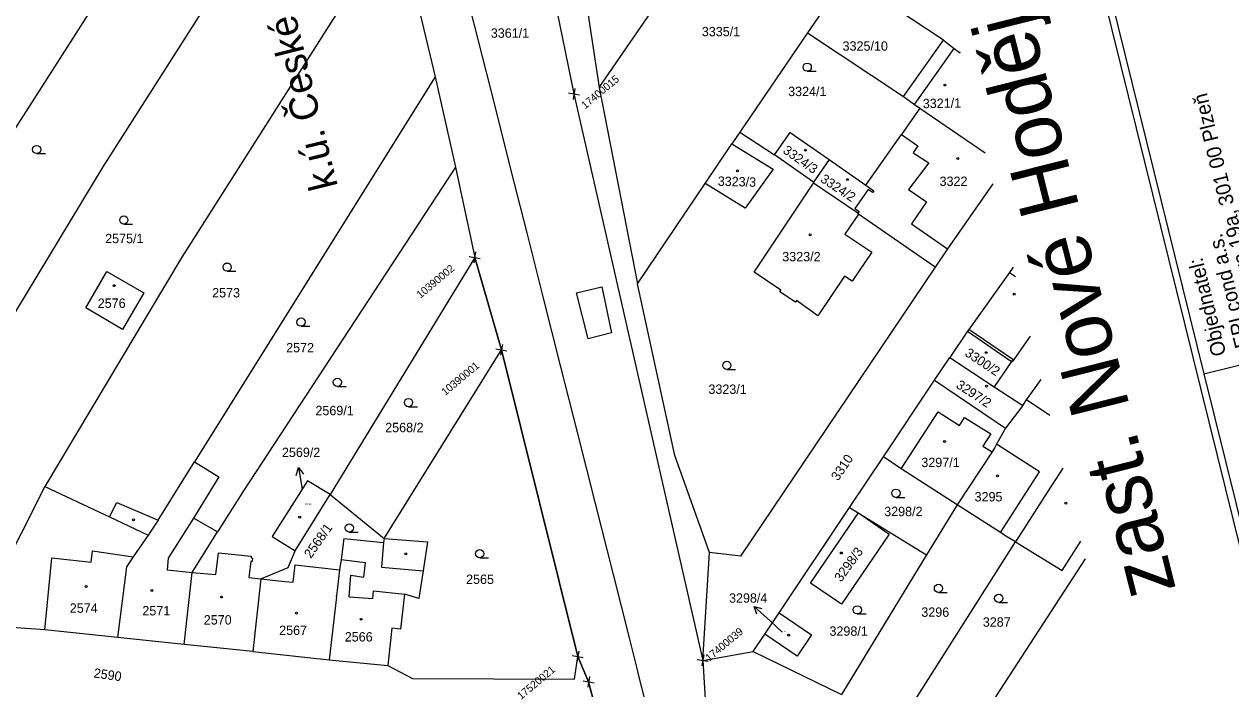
# Model space of a CAD drawing. Extents: x -754679 to -754173, y -1169241 to -1168288.
# Drawn here: x -754471.3 to -754307.2, y -1168949.2 to -1168858.8 of the extents above; entities that cross this region are included whole.
import ezdxf

# ---------------------------------------------------------------- set-up
doc = ezdxf.new("R2010")
doc.units = 0
for name, color, linetype in [('Vrstva 1', 7, 'Continuous'), ('Vrstva 16', 7, 'Continuous'), ('Vrstva 18', 7, 'Continuous'), ('Vrstva 19', 7, 'Continuous'), ('Vrstva 2', 7, 'Continuous'), ('Vrstva 23', 7, 'Continuous'), ('Vrstva 24', 7, 'Continuous'), ('Vrstva 25', 7, 'Continuous'), ('Vrstva 4', 7, 'Continuous'), ('Vrstva 52', 7, 'Continuous'), ('Vrstva 53', 7, 'Continuous'), ('Vrstva 60', 7, 'Continuous')]:
    doc.layers.add(name, color=color, linetype=linetype)

msp = doc.modelspace()

# ---------------------------------------------------------------- linework, layer by layer
at = {"layer": 'Vrstva 1'}
for p, q in [((-754477.37, -1168880.54), (-754443.28, -1168827.28)), ((-754393.12, -1168867.44), (-754373.15, -1168838.34)), ((-754420.6, -1168844.33), (-754449.89, -1168890.49)), ((-754420.6, -1168844.33), (-754415.45, -1168865.96)), ((-754401.41, -1168844.82), (-754396.56, -1168868.29)), ((-754396.3, -1168846.57), (-754393.12, -1168867.44)), ((-754460.56, -1168878.23), (-754444.22, -1168852.55)), ((-754359.46, -1168852.25), (-754364.83, -1168859.96)), ((-754346.33, -1168861), (-754359.46, -1168852.25)), ((-754364.83, -1168859.96), (-754374.01, -1168873.5)), ((-754364.83, -1168859.96), (-754351.77, -1168868.65)), ((-754346.33, -1168861), (-754344.87, -1168862.11)), ((-754350.27, -1168869.71), (-754344.87, -1168862.11)), ((-754344.87, -1168862.11), (-754344.14, -1168862.67)), ((-754344.07, -1168862.58), (-754344.14, -1168862.67)), ((-754344.14, -1168862.67), (-754344.03, -1168862.74)), ((-754415.45, -1168865.96), (-754448.17, -1168918.32)), ((-754415.45, -1168865.96), (-754412.65, -1168878.24)), ((-754396.56, -1168868.29), (-754379.05, -1168945.33)), ((-754393.12, -1168867.44), (-754387.93, -1168894.11)), ((-754351.77, -1168868.65), (-754350.27, -1168869.71)), ((-754350.27, -1168869.71), (-754349.52, -1168870.24)), ((-754349.52, -1168870.24), (-754352.02, -1168873.79)), ((-754349.52, -1168870.24), (-754340.67, -1168876.32)), ((-754374.01, -1168873.5), (-754375.09, -1168875.1)), ((-754374.01, -1168873.5), (-754369.28, -1168876.59)), ((-754369.28, -1168876.59), (-754367.16, -1168873.52)), ((-754367.16, -1168873.52), (-754361.87, -1168877.22)), ((-754356.89, -1168880.71), (-754352.02, -1168873.79)), ((-754378.72, -1168880.46), (-754375.09, -1168875.1)), ((-754375.09, -1168875.1), (-754369.49, -1168878.51)), ((-754364, -1168880.28), (-754369.28, -1168876.59)), ((-754472.47, -1168897.88), (-754460.56, -1168878.23)), ((-754412.65, -1168878.24), (-754441.58, -1168922.39)), ((-754412.65, -1168878.24), (-754410.06, -1168890.53)), ((-754361.87, -1168877.22), (-754364, -1168880.28)), ((-754361.87, -1168877.22), (-754356.89, -1168880.71)), ((-754369.49, -1168878.51), (-754373.29, -1168883.84)), ((-754387.93, -1168894.11), (-754378.72, -1168880.46)), ((-754373.29, -1168883.84), (-754378.72, -1168880.46)), ((-754372.07, -1168892.52), (-754363.97, -1168880.43)), ((-754363.97, -1168880.43), (-754364, -1168880.28)), ((-754357.95, -1168884.51), (-754363.97, -1168880.43)), ((-754356.58, -1168881.29), (-754358.39, -1168883.88)), ((-754356.89, -1168880.71), (-754355.81, -1168881.46)), ((-754355.99, -1168881.71), (-754356.58, -1168881.29)), ((-754355.81, -1168881.46), (-754355.99, -1168881.71)), ((-754339.63, -1168880.52), (-754345.75, -1168889.37)), ((-754357.88, -1168884.63), (-754359.73, -1168887.36)), ((-754358.39, -1168883.88), (-754357.79, -1168884.3)), ((-754357.79, -1168884.3), (-754357.95, -1168884.51)), ((-754357.88, -1168884.63), (-754357.95, -1168884.51)), ((-754347.46, -1168891.84), (-754357.88, -1168884.63)), ((-754359.73, -1168887.36), (-754356.08, -1168889.81)), ((-754356.08, -1168889.81), (-754358.74, -1168893.78)), ((-754345.75, -1168889.37), (-754347.46, -1168891.84)), ((-754449.89, -1168890.49), (-754468.49, -1168921.69)), ((-754410.06, -1168890.53), (-754429.73, -1168922.78)), ((-754410.06, -1168890.53), (-754406.43, -1168903.09)), ((-754462.92, -1168897.4), (-754460.07, -1168892.45)), ((-754460.07, -1168892.45), (-754455.03, -1168895.36)), ((-754347.46, -1168891.84), (-754373.92, -1168931.14)), ((-754368.43, -1168894.96), (-754372.07, -1168892.52)), ((-754359.8, -1168893.07), (-754363.42, -1168898.49)), ((-754358.74, -1168893.78), (-754359.8, -1168893.07)), ((-754337.33, -1168892.56), (-754342.88, -1168900.34)), ((-754336.83, -1168891.86), (-754337.33, -1168892.56)), ((-754337.33, -1168892.56), (-754336.51, -1168893.14)), ((-754382.87, -1168917.47), (-754387.93, -1168894.11)), ((-754455.03, -1168895.36), (-754457.95, -1168900.33)), ((-754368.59, -1168895.19), (-754368.43, -1168894.96)), ((-754366.44, -1168896.63), (-754368.59, -1168895.19)), ((-754457.95, -1168900.33), (-754462.92, -1168897.4)), ((-754366.29, -1168896.39), (-754366.44, -1168896.63)), ((-754363.42, -1168898.49), (-754366.29, -1168896.39)), ((-754343.03, -1168900.56), (-754345.45, -1168904.13)), ((-754342.88, -1168900.34), (-754343.03, -1168900.56)), ((-754336.88, -1168904.4), (-754342.88, -1168900.34)), ((-754334.51, -1168901.23), (-754337, -1168904.73)), ((-754422.39, -1168928.77), (-754406.43, -1168903.09)), ((-754406.43, -1168903.09), (-754396.05, -1168944.82)), ((-754347.54, -1168907.23), (-754345.45, -1168904.13)), ((-754345.45, -1168904.13), (-754339.41, -1168908.11)), ((-754336.88, -1168904.4), (-754337.07, -1168904.68)), ((-754337.07, -1168904.68), (-754339.41, -1168908.11)), ((-754337, -1168904.73), (-754337.07, -1168904.68)), ((-754354.49, -1168917.65), (-754347.54, -1168907.23)), ((-754347.54, -1168907.23), (-754337.87, -1168913.75)), ((-754335.01, -1168909.89), (-754333.05, -1168907.14)), ((-754339.41, -1168908.11), (-754335.55, -1168910.65)), ((-754335.55, -1168910.65), (-754337.87, -1168913.75)), ((-754335.55, -1168910.65), (-754335.01, -1168909.89)), ((-754331.84, -1168912.03), (-754335.01, -1168909.89)), ((-754337.87, -1168913.75), (-754339.09, -1168915.92)), ((-754339.09, -1168915.92), (-754339.34, -1168916.37)), ((-754378.13, -1168930.64), (-754382.87, -1168917.47)), ((-754359.09, -1168924.53), (-754354.49, -1168917.65)), ((-754352.09, -1168919.27), (-754354.49, -1168917.65)), ((-754339.72, -1168916.96), (-754344.47, -1168924.17)), ((-754339.34, -1168916.37), (-754339.72, -1168916.96)), ((-754453.08, -1168926.28), (-754448.17, -1168918.32)), ((-754448.17, -1168918.32), (-754444.86, -1168920.39)), ((-754344.47, -1168924.17), (-754352.09, -1168919.27)), ((-754330.08, -1168919.18), (-754332.16, -1168922.4)), ((-754444.86, -1168920.39), (-754448.28, -1168926)), ((-754432.81, -1168920.9), (-754437.59, -1168928.48)), ((-754429.73, -1168922.78), (-754432.81, -1168920.9)), ((-754468.49, -1168921.69), (-754478.02, -1168940.49)), ((-754468.49, -1168921.69), (-754459.74, -1168925.82)), ((-754441.58, -1168922.39), (-754445.02, -1168927.83)), ((-754332.16, -1168922.4), (-754336.53, -1168929.23)), ((-754459.74, -1168925.82), (-754458.72, -1168923.88)), ((-754458.72, -1168923.88), (-754453.08, -1168926.28)), ((-754434.48, -1168930.44), (-754429.73, -1168922.78)), ((-754429.73, -1168922.78), (-754422.39, -1168928.77)), ((-754344.47, -1168924.17), (-754348.61, -1168930.98)), ((-754338.58, -1168927.96), (-754344.47, -1168924.17)), ((-754368.68, -1168938.89), (-754359.09, -1168924.53)), ((-754364.41, -1168934.84), (-754357.89, -1168925.29)), ((-754359.09, -1168924.53), (-754348.61, -1168930.98)), ((-754357.89, -1168925.29), (-754353.69, -1168928.15)), ((-754453.08, -1168926.28), (-754454.46, -1168928.29)), ((-754445.02, -1168927.83), (-754448.28, -1168926)), ((-754454.46, -1168928.29), (-754456.49, -1168931.25)), ((-754448.49, -1168933.38), (-754445.02, -1168927.83)), ((-754437.59, -1168928.48), (-754434.48, -1168930.44)), ((-754427.85, -1168928.75), (-754428.24, -1168931.61)), ((-754427.85, -1168928.75), (-754422.44, -1168929.31)), ((-754422.39, -1168928.77), (-754422.44, -1168929.31)), ((-754422.39, -1168928.77), (-754416.46, -1168929.19)), ((-754416.46, -1168929.19), (-754417.07, -1168933.14)), ((-754353.69, -1168928.15), (-754360.19, -1168937.71)), ((-754337.83, -1168928.44), (-754338.58, -1168927.96)), ((-754336.53, -1168929.23), (-754337.83, -1168928.44)), ((-754330.19, -1168933.13), (-754327.62, -1168929.11)), ((-754445.25, -1168933.67), (-754444.92, -1168930.69)), ((-754444.92, -1168930.69), (-754440.44, -1168931.16)), ((-754435.41, -1168932.72), (-754434.48, -1168930.44)), ((-754379.05, -1168945.33), (-754378.13, -1168930.64)), ((-754373.92, -1168931.14), (-754378.13, -1168930.64)), ((-754351.06, -1168952.16), (-754336.53, -1168929.23)), ((-754336.53, -1168929.23), (-754330.19, -1168933.13)), ((-754456.49, -1168931.25), (-754457.42, -1168932.6)), ((-754440.52, -1168931.87), (-754440.77, -1168934.08)), ((-754440.31, -1168931.89), (-754440.52, -1168931.87)), ((-754440.44, -1168931.16), (-754440.47, -1168931.4)), ((-754440.47, -1168931.4), (-754440.26, -1168931.42)), ((-754440.26, -1168931.42), (-754440.31, -1168931.89)), ((-754434.76, -1168934.72), (-754434.48, -1168932.33)), ((-754434.48, -1168932.33), (-754428.45, -1168933.04)), ((-754428.24, -1168931.61), (-754428.45, -1168933.04)), ((-754348.61, -1168930.98), (-754360.17, -1168949.97)), ((-754341.72, -1168954.18), (-754327.02, -1168931.53)), ((-754457.42, -1168932.6), (-754458.62, -1168942.21)), ((-754449.57, -1168943.16), (-754448.49, -1168933.38)), ((-754448.49, -1168933.38), (-754445.25, -1168933.67)), ((-754440.77, -1168934.08), (-754439.14, -1168934.23)), ((-754439.14, -1168934.23), (-754435.41, -1168932.72)), ((-754428.45, -1168933.04), (-754428.84, -1168936.55)), ((-754417.07, -1168933.14), (-754417.65, -1168936.92)), ((-754439.14, -1168934.23), (-754440.24, -1168944.14)), ((-754439.14, -1168934.23), (-754435.9, -1168934.59)), ((-754435.9, -1168934.59), (-754434.76, -1168934.72)), ((-754360.19, -1168937.71), (-754364.41, -1168934.84)), ((-754428.86, -1168936.68), (-754429.85, -1168945.24)), ((-754428.86, -1168936.68), (-754428.84, -1168936.55)), ((-754419.59, -1168936.35), (-754420.13, -1168941.08)), ((-754417.65, -1168936.92), (-754419.59, -1168936.35)), ((-754370.59, -1168941.76), (-754368.68, -1168938.89)), ((-754368.68, -1168938.89), (-754364.27, -1168941.87)), ((-754468.53, -1168941.18), (-754478.02, -1168940.49)), ((-754458.62, -1168942.21), (-754468.53, -1168941.18)), ((-754449.57, -1168943.16), (-754458.62, -1168942.21)), ((-754421.31, -1168940.95), (-754421.89, -1168946.03)), ((-754420.13, -1168941.08), (-754421.31, -1168940.95)), ((-754372.18, -1168944.13), (-754370.59, -1168941.76)), ((-754366.21, -1168944.75), (-754370.59, -1168941.76)), ((-754364.27, -1168941.87), (-754366.21, -1168944.75)), ((-754440.24, -1168944.14), (-754449.57, -1168943.16)), ((-754440.24, -1168944.14), (-754429.85, -1168945.24)), ((-754429.85, -1168945.24), (-754421.89, -1168946.03)), ((-754396.5, -1168947.91), (-754396.05, -1168944.82)), ((-754396.05, -1168944.82), (-754394.57, -1168948.26)), ((-754379.05, -1168945.33), (-754372.18, -1168944.13)), ((-754379.05, -1168945.33), (-754378.16, -1168960.13)), ((-754372.18, -1168944.13), (-754360.17, -1168949.97)), ((-754421.89, -1168946.03), (-754418.54, -1168947.81)), ((-754418.54, -1168947.81), (-754396.5, -1168947.91)), ((-754394.57, -1168948.26), (-754386.06, -1168980.52))]:
    msp.add_line(p, q, dxfattribs=at)
for points in [[(-754398.29, -1168905.57), (-754400.74, -1168895.89), (-754402.94, -1168887.2), (-754405.13, -1168878.51), (-754407.34, -1168869.78), (-754409.54, -1168861.07), (-754411.98, -1168851.4), (-754414.17, -1168842.73), (-754415.89, -1168835.94), (-754418.06, -1168827.34), (-754420.43, -1168817.97), (-754422.09, -1168811.41)], [(-754384.66, -1168959.57), (-754385.94, -1168954.49), (-754386.73, -1168951.32), (-754387.86, -1168946.89), (-754387.93, -1168946.6), (-754389.02, -1168942.29), (-754391.2, -1168933.67), (-754393.65, -1168923.98), (-754396.08, -1168914.31), (-754398.29, -1168905.57)]]:
    msp.add_lwpolyline(points, dxfattribs=at)
at = {"layer": 'Vrstva 16'}
for p, q in [((-754434, -1168919.1), (-754433.5, -1168922.06)), ((-754372.08, -1168937.99), (-754369.86, -1168940.01)), ((-754368.24, -1168941.48), (-754369.86, -1168940.01))]:
    msp.add_line(p, q, dxfattribs=at)
for points in [[(-754434.33, -1168920.17), (-754434, -1168919.1), (-754433.34, -1168920.01)], [(-754371.68, -1168939.03), (-754372.08, -1168937.99), (-754371, -1168938.29)]]:
    msp.add_lwpolyline(points, dxfattribs=at)
at = {"layer": 'Vrstva 2'}
for p, q in [((-754296.3, -1168969.17), (-754339.93, -1168792.71)), ((-754326.19, -1168844.61), (-754310.92, -1168906.35)), ((-754310.92, -1168906.35), (-754296.17, -1168902.71)), ((-754310.92, -1168906.35), (-754295.65, -1168968.1))]:
    msp.add_line(p, q, dxfattribs=at)
at = {"layer": 'Vrstva 25'}
for p, q in [((-754364.85, -1168865.21), (-754363.65, -1168865.21)), ((-754469.62, -1168876.41), (-754468.42, -1168876.41)), ((-754457.77, -1168886), (-754456.57, -1168886)), ((-754443.72, -1168892.41), (-754442.52, -1168892.41)), ((-754433.67, -1168899.89), (-754432.47, -1168899.89)), ((-754375.78, -1168905.77), (-754374.58, -1168905.77)), ((-754428.73, -1168908.07), (-754427.53, -1168908.07)), ((-754419.06, -1168910.83), (-754417.86, -1168910.83)), ((-754352.79, -1168923.16), (-754351.59, -1168923.16)), ((-754427.11, -1168927.88), (-754425.91, -1168927.88)), ((-754409.38, -1168931.38), (-754408.18, -1168931.38)), ((-754347, -1168936.09), (-754345.8, -1168936.09)), ((-754358.05, -1168939.02), (-754356.85, -1168939.02)), ((-754338.8, -1168937.45), (-754337.6, -1168937.45))]:
    msp.add_line(p, q, dxfattribs=at)
for centre, radius in [((-754364.85, -1168864.65), 0.562), ((-754346.13, -1168867.08), 0.131), ((-754469.62, -1168875.85), 0.562), ((-754365.07, -1168875.96), 0.131), ((-754344.36, -1168877.08), 0.131), ((-754374.31, -1168878.76), 0.131), ((-754359.36, -1168879.95), 0.131), ((-754457.77, -1168885.44), 0.562), ((-754364.46, -1168887.44), 0.131), ((-754443.72, -1168891.85), 0.562), ((-754459.09, -1168894.37), 0.131), ((-754336.71, -1168895.52), 0.131), ((-754433.67, -1168899.33), 0.562), ((-754340.5, -1168903.48), 0.131), ((-754375.78, -1168905.21), 0.562), ((-754428.73, -1168907.51), 0.562), ((-754340.46, -1168908.03), 0.131), ((-754419.06, -1168910.27), 0.562), ((-754346.19, -1168915.58), 0.131), ((-754338.96, -1168920.25), 0.131), ((-754352.79, -1168922.6), 0.562), ((-754329.68, -1168923.96), 0.131), ((-754433.86, -1168925.87), 0.131), ((-754456.44, -1168926.22), 0.131), ((-754427.11, -1168927.32), 0.562), ((-754419.44, -1168930.85), 0.131), ((-754409.38, -1168930.82), 0.562), ((-754360.21, -1168930.73), 0.131), ((-754462.89, -1168935.3), 0.131), ((-754453.97, -1168935.83), 0.131), ((-754347, -1168935.53), 0.562), ((-754444.48, -1168936.72), 0.131), ((-754338.8, -1168936.89), 0.562), ((-754434.3, -1168938.91), 0.131), ((-754358.05, -1168938.46), 0.562), ((-754425.51, -1168939.75), 0.131), ((-754367.37, -1168941.89), 0.131)]:
    msp.add_circle(centre, radius, dxfattribs=at)
at = {"layer": 'Vrstva 4'}
for p, q in [((-754351.77, -1168868.65), (-754346.33, -1168861)), ((-754352.02, -1168873.79), (-754349.8, -1168875.35)), ((-754349.8, -1168875.35), (-754350.46, -1168876.3)), ((-754350.46, -1168876.3), (-754348.31, -1168877.68)), ((-754348.31, -1168877.68), (-754351.08, -1168881.29)), ((-754351.08, -1168881.29), (-754348.63, -1168882.99)), ((-754348.63, -1168882.99), (-754350.68, -1168885.96)), ((-754350.68, -1168885.96), (-754345.75, -1168889.37)), ((-754396.22, -1168895.33), (-754392.79, -1168894.53)), ((-754392.79, -1168894.53), (-754391.44, -1168900.79)), ((-754394.61, -1168901.6), (-754396.22, -1168895.33)), ((-754391.44, -1168900.79), (-754394.61, -1168901.6)), ((-754343.03, -1168900.56), (-754337.07, -1168904.68)), ((-754352.09, -1168919.27), (-754347.05, -1168911.55)), ((-754347.05, -1168911.55), (-754344.13, -1168913.38)), ((-754344.13, -1168913.38), (-754343.45, -1168912.29)), ((-754343.45, -1168912.29), (-754339.9, -1168914.51)), ((-754339.9, -1168914.51), (-754340.95, -1168916.19)), ((-754333.25, -1168919.67), (-754339.09, -1168915.92)), ((-754340.95, -1168916.19), (-754339.72, -1168916.96)), ((-754338.58, -1168927.96), (-754333.25, -1168919.67)), ((-754459.74, -1168925.82), (-754454.46, -1168928.29)), ((-754448.28, -1168926), (-754451.73, -1168931.44)), ((-754462.19, -1168931.99), (-754462.02, -1168930.44)), ((-754462.02, -1168930.44), (-754456.49, -1168931.25)), ((-754422.44, -1168929.31), (-754422.75, -1168932.64)), ((-754468.53, -1168941.18), (-754467.54, -1168931.41)), ((-754467.54, -1168931.41), (-754462.19, -1168931.99)), ((-754451.73, -1168931.44), (-754451.89, -1168933.04)), ((-754428.24, -1168931.61), (-754424.95, -1168932.04)), ((-754424.95, -1168932.04), (-754425.19, -1168934)), ((-754451.89, -1168933.04), (-754448.49, -1168933.38)), ((-754427.12, -1168936.68), (-754426.91, -1168933.76)), ((-754426.91, -1168933.76), (-754425.19, -1168934)), ((-754422.75, -1168932.64), (-754417.07, -1168933.14)), ((-754427.12, -1168936.68), (-754423.92, -1168936.91)), ((-754423.92, -1168936.91), (-754423.8, -1168935.86)), ((-754423.8, -1168935.86), (-754419.59, -1168936.35))]:
    msp.add_line(p, q, dxfattribs=at)
at = {"layer": 'Vrstva 53'}
for p, q in [((-754396.56, -1168868.29), (-754379.05, -1168945.33)), ((-754406.43, -1168903.09), (-754410.06, -1168890.53)), ((-754396.05, -1168944.82), (-754406.43, -1168903.09)), ((-754394.57, -1168948.26), (-754396.05, -1168944.82)), ((-754379.05, -1168945.33), (-754378.16, -1168960.13))]:
    msp.add_line(p, q, dxfattribs=at)
msp.add_lwpolyline([(-754345.91, -1169130.8), (-754386.06, -1168980.52), (-754394.57, -1168948.26)], dxfattribs=at)
at = {"layer": 'Vrstva 60'}
for p, q in [((-754397.3, -1168868.16), (-754395.82, -1168868.42)), ((-754396.43, -1168867.55), (-754396.69, -1168869.03)), ((-754409.93, -1168889.79), (-754410.19, -1168891.27)), ((-754410.8, -1168890.4), (-754409.32, -1168890.66)), ((-754406.3, -1168902.35), (-754406.56, -1168903.83)), ((-754407.17, -1168902.96), (-754405.69, -1168903.22)), ((-754396.79, -1168944.69), (-754395.31, -1168944.95)), ((-754395.92, -1168944.08), (-754396.18, -1168945.56)), ((-754379.79, -1168945.2), (-754378.31, -1168945.46)), ((-754378.92, -1168944.59), (-754379.18, -1168946.07)), ((-754395.31, -1168948.13), (-754393.83, -1168948.39)), ((-754394.44, -1168947.52), (-754394.7, -1168949))]:
    msp.add_line(p, q, dxfattribs=at)

# ---------------------------------------------------------------- texts
at = {"layer": 'Vrstva 16'}
for s, p in [('2569/2', (-754436.27, -1168917.68)), ('3298/4', (-754375.48, -1168937.49))]:
    msp.add_text(s, height=1.275, rotation=360, dxfattribs=at).set_placement(p)
at = {"layer": 'Vrstva 18'}
for s, rotation, p in [('3361/1', 360, (-754407.87, -1168860.65)), ('3335/1', 360, (-754379.18, -1168860.45)), ('3325/10', 360, (-754360.04, -1168862.41)), ('3324/1', 360, (-754367.44, -1168868.59)), ('2575/1', 360, (-754460.31, -1168888.59)), ('2573', 360, (-754445.76, -1168895.97)), ('2572', 360, (-754435.7, -1168903.44)), ('3323/1', 360, (-754378.28, -1168909.09)), ('2569/1', 360, (-754431.72, -1168911.99)), ('2568/2', 360, (-754422.23, -1168914.3)), ('3310', 55.8061, (-754360.65, -1168921.01)), ('3298/2', 360, (-754354.38, -1168925.72)), ('2568/1', 54.8894, (-754432.33, -1168931.55)), ('2565', 360, (-754411.23, -1168934.94)), ('3296', 360, (-754349.33, -1168939.41)), ('3298/1', 360, (-754361.82, -1168941.99)), ('3287', 360, (-754340.97, -1168940.76)), ('2590', 351.9107, (-754461.93, -1168947.65))]:
    msp.add_text(s, height=1.275, rotation=rotation, dxfattribs=at).set_placement(p)
at = {"layer": 'Vrstva 19'}
for s, rotation, p in [('3321/1', 1.0886, (-754349.12, -1168870.24)), ('3324/3', 324.9244, (-754368.26, -1168876.23)), ('3323/3', 358.3851, (-754377.03, -1168880.78)), ('3324/2', 326.6432, (-754363.16, -1168880.16)), ('3322', 360, (-754346.85, -1168880.81)), ('3323/2', 360, (-754368.24, -1168891.06)), ('2576', 360, (-754461.32, -1168897.39)), ('3300/2', 326.2422, (-754343.52, -1168903.82)), ('3297/2', 326.7005, (-754344.71, -1168908.17)), ('3297/1', 360, (-754349.33, -1168919.05)), ('3295', 360, (-754342.09, -1168923.72)), ('3298/3', 53.9726, (-754360.24, -1168934.76)), ('2574', 360, (-754465.12, -1168938.86)), ('2571', 360, (-754455.25, -1168939.22)), ('2570', 360, (-754446.9, -1168940.46)), ('2567', 360, (-754436.65, -1168941.88)), ('2566', 360, (-754427.73, -1168942.77))]:
    msp.add_text(s, height=1.275, rotation=rotation, dxfattribs=at).set_placement(p)
for s, height, p in [('2569/2', 0.2, (-754433.12, -1168924.18)), ('3298/4', 0.1, (-754368.23, -1168941.48))]:
    msp.add_text(s, height=height, dxfattribs=at).set_placement(p)
at = {"layer": 'Vrstva 2'}
for s, p in [('Purkyňova 19a, 301 00 Plzeň', (-754302.13, -1168901.96)), ('EPLcond a.s.', (-754304.65, -1168902.58)), ('Objednatel:', (-754307.85, -1168903.7))]:
    msp.add_text(s, height=2, rotation=103.8896, dxfattribs=at).set_placement(p)
at = {"layer": 'Vrstva 23'}
msp.add_text('zast. Nové Hodějovice', height=8, rotation=104.1786, dxfattribs=at).set_placement((-754314.68, -1168935.68))
at = {"layer": 'Vrstva 24'}
msp.add_text('k.ú. České Budějovice 6', height=3.84, rotation=103.8896, dxfattribs=at).set_placement((-754428.65, -1168880.86))
at = {"layer": 'Vrstva 52'}
for s, p in [(' 17400015', (-754395.33, -1168870.65)), (' 10390002', (-754417.73, -1168896.41)), (' 10390001', (-754414.35, -1168909.63)), (' 17400039', (-754378.47, -1168945.79)), (' 17520021', (-754404.04, -1168950.98))]:
    msp.add_text(s, height=1.037, rotation=40, dxfattribs=at).set_placement(p)

doc.saveas('drawing.dxf')
